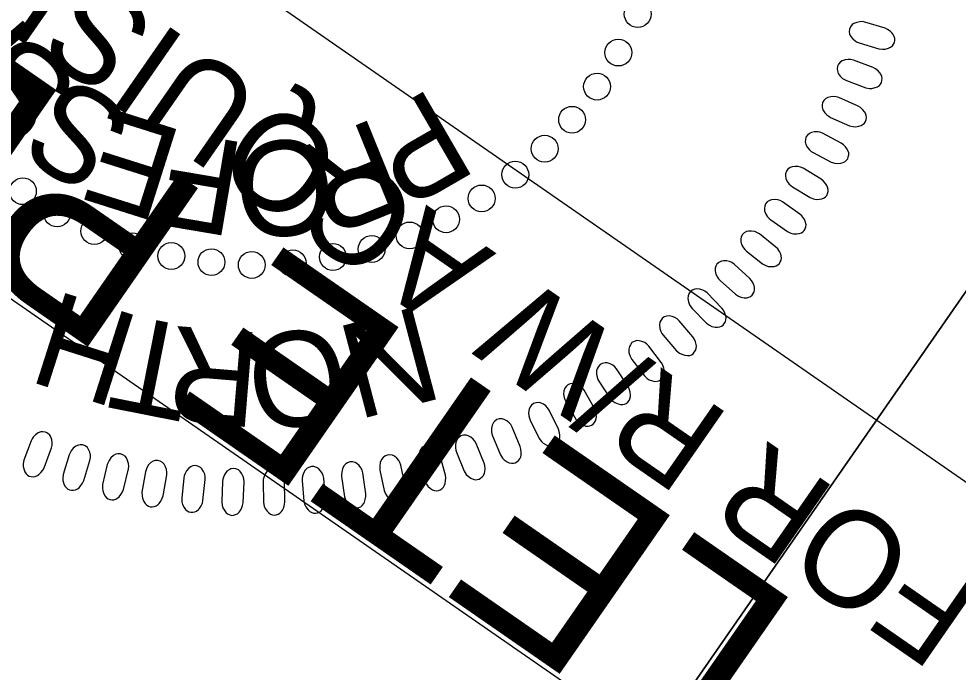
# Model space of a CAD drawing. Extents: x 478372 to 480379, y 492840 to 494699.
# Drawn here: x 478483.3 to 478539.3, y 493813.2 to 493852.2 of the extents above; entities that cross this region are included whole.
import ezdxf

# ---------------------------------------------------------------- set-up
doc = ezdxf.new("R2010")
doc.units = 0
for name, color, linetype in [('Sheet PE Seal Cell', 7, 'Continuous'), ('Sheet Plan CELL', 7, 'Continuous'), ('Sheet Sticker Exception Certification CELL', 7, 'Continuous'), ('Sheet Sticker Incomplete CELL', 7, 'Continuous')]:
    doc.layers.add(name, color=color, linetype=linetype)

msp = doc.modelspace()

# ---------------------------------------------------------------- linework, layer by layer
at = {"layer": 'Sheet PE Seal Cell'}
for points in [[(478533.439, 493850.734), (478534.613, 493850.38), (478534.834, 493850.353), (478534.983, 493850.362), (478535.178, 493850.421), (478535.311, 493850.483), (478535.42, 493850.567), (478535.488, 493850.655), (478535.539, 493850.757), (478535.552, 493850.87), (478535.558, 493850.993), (478535.531, 493851.11), (478535.466, 493851.239), (478535.407, 493851.32), (478535.283, 493851.427), (478535.128, 493851.536), (478534.982, 493851.604), (478533.781, 493851.974), (478533.612, 493852.001), (478533.466, 493851.998), (478533.287, 493851.958), (478533.121, 493851.891), (478533.016, 493851.821), (478532.914, 493851.688), (478532.852, 493851.551), (478532.847, 493851.396), (478532.864, 493851.282), (478532.923, 493851.132), (478533.051, 493850.968), (478533.203, 493850.852), (478533.319, 493850.786)], [(478532.674, 493848.485), (478533.824, 493848.058), (478534.043, 493848.017), (478534.192, 493848.016), (478534.39, 493848.063), (478534.527, 493848.116), (478534.641, 493848.194), (478534.714, 493848.278), (478534.772, 493848.376), (478534.792, 493848.487), (478534.806, 493848.61), (478534.787, 493848.729), (478534.729, 493848.862), (478534.675, 493848.946), (478534.559, 493849.061), (478534.411, 493849.18), (478534.269, 493849.256), (478533.094, 493849.701), (478532.927, 493849.739), (478532.781, 493849.745), (478532.6, 493849.716), (478532.43, 493849.66), (478532.322, 493849.597), (478532.21, 493849.47), (478532.14, 493849.337), (478532.125, 493849.183), (478532.136, 493849.067), (478532.184, 493848.913), (478532.302, 493848.743), (478532.447, 493848.617), (478532.558, 493848.544)], [(478531.734, 493846.288), (478532.855, 493845.79), (478533.071, 493845.735), (478533.219, 493845.725), (478533.42, 493845.759), (478533.56, 493845.803), (478533.678, 493845.874), (478533.757, 493845.953), (478533.821, 493846.047), (478533.848, 493846.158), (478533.869, 493846.279), (478533.857, 493846.399), (478533.808, 493846.535), (478533.76, 493846.622), (478533.651, 493846.745), (478533.511, 493846.872), (478533.374, 493846.958), (478532.229, 493847.475), (478532.065, 493847.523), (478531.919, 493847.539), (478531.737, 493847.522), (478531.564, 493847.476), (478531.451, 493847.42), (478531.333, 493847.301), (478531.254, 493847.172), (478531.23, 493847.019), (478531.233, 493846.903), (478531.272, 493846.747), (478531.379, 493846.569), (478531.516, 493846.434), (478531.622, 493846.355)], [(478530.682, 493844.187), (478531.77, 493843.619), (478531.982, 493843.551), (478532.13, 493843.532), (478532.332, 493843.554), (478532.474, 493843.589), (478532.597, 493843.652), (478532.68, 493843.726), (478532.75, 493843.816), (478532.784, 493843.925), (478532.813, 493844.044), (478532.809, 493844.165), (478532.768, 493844.304), (478532.725, 493844.394), (478532.624, 493844.523), (478532.492, 493844.659), (478532.362, 493844.752), (478531.251, 493845.341), (478531.091, 493845.399), (478530.946, 493845.424), (478530.763, 493845.419), (478530.588, 493845.384), (478530.472, 493845.335), (478530.346, 493845.223), (478530.259, 493845.1), (478530.225, 493844.949), (478530.221, 493844.833), (478530.25, 493844.674), (478530.345, 493844.49), (478530.474, 493844.347), (478530.575, 493844.261)], [(478529.46, 493842.137), (478530.51, 493841.502), (478530.717, 493841.42), (478530.864, 493841.392), (478531.067, 493841.401), (478531.212, 493841.427), (478531.338, 493841.482), (478531.426, 493841.551), (478531.501, 493841.637), (478531.541, 493841.743), (478531.578, 493841.861), (478531.581, 493841.981), (478531.55, 493842.122), (478531.513, 493842.215), (478531.419, 493842.349), (478531.297, 493842.494), (478531.172, 493842.595), (478530.1, 493843.252), (478529.943, 493843.321), (478529.801, 493843.354), (478529.618, 493843.36), (478529.441, 493843.337), (478529.322, 493843.295), (478529.189, 493843.192), (478529.095, 493843.074), (478529.052, 493842.925), (478529.04, 493842.81), (478529.06, 493842.65), (478529.143, 493842.46), (478529.262, 493842.309), (478529.358, 493842.216)], [(478528.16, 493840.17), (478529.168, 493839.47), (478529.369, 493839.376), (478529.514, 493839.339), (478529.717, 493839.335), (478529.863, 493839.352), (478529.992, 493839.399), (478530.084, 493839.462), (478530.165, 493839.543), (478530.212, 493839.646), (478530.256, 493839.761), (478530.267, 493839.881), (478530.244, 493840.024), (478530.213, 493840.119), (478530.128, 493840.26), (478530.015, 493840.411), (478529.897, 493840.52), (478528.868, 493841.243), (478528.717, 493841.321), (478528.576, 493841.364), (478528.394, 493841.381), (478528.215, 493841.369), (478528.094, 493841.335), (478527.956, 493841.24), (478527.854, 493841.128), (478527.802, 493840.982), (478527.783, 493840.868), (478527.792, 493840.707), (478527.863, 493840.512), (478527.973, 493840.354), (478528.062, 493840.256)], [(478526.713, 493838.312), (478527.675, 493837.551), (478527.87, 493837.444), (478528.012, 493837.398), (478528.215, 493837.381), (478528.361, 493837.389), (478528.493, 493837.427), (478528.589, 493837.485), (478528.675, 493837.56), (478528.728, 493837.661), (478528.779, 493837.773), (478528.798, 493837.892), (478528.784, 493838.036), (478528.759, 493838.132), (478528.683, 493838.278), (478528.58, 493838.436), (478528.469, 493838.553), (478527.488, 493839.339), (478527.341, 493839.427), (478527.204, 493839.478), (478527.023, 493839.506), (478526.844, 493839.506), (478526.721, 493839.479), (478526.577, 493839.393), (478526.468, 493839.288), (478526.407, 493839.146), (478526.381, 493839.033), (478526.38, 493838.871), (478526.439, 493838.673), (478526.538, 493838.508), (478526.621, 493838.405)], [(478525.142, 493836.55), (478526.054, 493835.73), (478526.242, 493835.611), (478526.381, 493835.555), (478526.582, 493835.526), (478526.728, 493835.524), (478526.863, 493835.555), (478526.962, 493835.606), (478527.052, 493835.676), (478527.112, 493835.772), (478527.17, 493835.882), (478527.196, 493835.999), (478527.191, 493836.144), (478527.172, 493836.242), (478527.106, 493836.392), (478527.012, 493836.556), (478526.909, 493836.68), (478525.979, 493837.526), (478525.838, 493837.622), (478525.704, 493837.682), (478525.526, 493837.722), (478525.347, 493837.732), (478525.222, 493837.713), (478525.073, 493837.637), (478524.958, 493837.539), (478524.888, 493837.401), (478524.855, 493837.29), (478524.844, 493837.129), (478524.891, 493836.926), (478524.979, 493836.756), (478525.055, 493836.647)], [(478523.477, 493834.888), (478524.336, 493834.012), (478524.516, 493833.881), (478524.651, 493833.817), (478524.851, 493833.775), (478524.996, 493833.765), (478525.133, 493833.787), (478525.235, 493833.831), (478525.329, 493833.895), (478525.395, 493833.988), (478525.459, 493834.093), (478525.492, 493834.209), (478525.497, 493834.354), (478525.484, 493834.453), (478525.428, 493834.607), (478525.344, 493834.777), (478525.249, 493834.906), (478524.374, 493835.81), (478524.239, 493835.914), (478524.109, 493835.982), (478523.934, 493836.034), (478523.756, 493836.055), (478523.631, 493836.044), (478523.477, 493835.977), (478523.356, 493835.886), (478523.277, 493835.753), (478523.238, 493835.644), (478523.217, 493835.484), (478523.25, 493835.279), (478523.328, 493835.104), (478523.397, 493834.99)], [(478521.749, 493833.293), (478522.551, 493832.365), (478522.723, 493832.223), (478522.854, 493832.151), (478523.049, 493832.097), (478523.194, 493832.077), (478523.332, 493832.089), (478523.437, 493832.128), (478523.535, 493832.187), (478523.606, 493832.274), (478523.678, 493832.376), (478523.718, 493832.49), (478523.731, 493832.633), (478523.725, 493832.733), (478523.678, 493832.89), (478523.605, 493833.065), (478523.518, 493833.2), (478522.702, 493834.156), (478522.574, 493834.27), (478522.449, 493834.346), (478522.277, 493834.408), (478522.101, 493834.44), (478521.975, 493834.437), (478521.817, 493834.38), (478521.691, 493834.297), (478521.604, 493834.169), (478521.557, 493834.063), (478521.526, 493833.904), (478521.547, 493833.698), (478521.613, 493833.518), (478521.676, 493833.401)], [(478519.884, 493831.841), (478520.627, 493830.864), (478520.789, 493830.713), (478520.915, 493830.632), (478521.107, 493830.565), (478521.251, 493830.537), (478521.389, 493830.541), (478521.495, 493830.573), (478521.597, 493830.625), (478521.674, 493830.709), (478521.751, 493830.805), (478521.798, 493830.915), (478521.822, 493831.058), (478521.821, 493831.158), (478521.784, 493831.318), (478521.723, 493831.497), (478521.644, 493831.638), (478520.89, 493832.643), (478520.769, 493832.764), (478520.649, 493832.848), (478520.481, 493832.921), (478520.308, 493832.964), (478520.182, 493832.969), (478520.021, 493832.922), (478519.89, 493832.847), (478519.795, 493832.725), (478519.742, 493832.622), (478519.7, 493832.466), (478519.708, 493832.258), (478519.763, 493832.074), (478519.818, 493831.953)], [(478517.917, 493830.541), (478518.596, 493829.52), (478518.749, 493829.358), (478518.87, 493829.27), (478519.057, 493829.191), (478519.199, 493829.154), (478519.336, 493829.15), (478519.446, 493829.175), (478519.55, 493829.22), (478519.632, 493829.299), (478519.715, 493829.39), (478519.769, 493829.497), (478519.801, 493829.638), (478519.807, 493829.738), (478519.78, 493829.9), (478519.73, 493830.083), (478519.661, 493830.228), (478518.971, 493831.278), (478518.858, 493831.407), (478518.743, 493831.498), (478518.581, 493831.582), (478518.41, 493831.636), (478518.285, 493831.648), (478518.12, 493831.612), (478517.986, 493831.545), (478517.883, 493831.429), (478517.824, 493831.329), (478517.773, 493831.176), (478517.767, 493830.969), (478517.811, 493830.782), (478517.858, 493830.657)], [(478515.937, 493829.336), (478516.551, 493828.274), (478516.693, 493828.102), (478516.809, 493828.007), (478516.991, 493827.917), (478517.13, 493827.871), (478517.267, 493827.858), (478517.377, 493827.876), (478517.484, 493827.915), (478517.571, 493827.988), (478517.66, 493828.074), (478517.72, 493828.177), (478517.761, 493828.316), (478517.773, 493828.415), (478517.756, 493828.579), (478517.718, 493828.764), (478517.658, 493828.914), (478517.035, 493830.006), (478516.931, 493830.141), (478516.822, 493830.239), (478516.665, 493830.332), (478516.498, 493830.397), (478516.374, 493830.417), (478516.208, 493830.391), (478516.068, 493830.333), (478515.96, 493830.224), (478515.893, 493830.128), (478515.833, 493829.978), (478515.814, 493829.772), (478515.846, 493829.583), (478515.886, 493829.455)], [(478513.816, 493828.223), (478514.362, 493827.124), (478514.493, 493826.944), (478514.602, 493826.842), (478514.778, 493826.741), (478514.914, 493826.686), (478515.05, 493826.664), (478515.161, 493826.675), (478515.27, 493826.707), (478515.362, 493826.775), (478515.456, 493826.855), (478515.523, 493826.955), (478515.572, 493827.091), (478515.59, 493827.189), (478515.584, 493827.353), (478515.557, 493827.54), (478515.506, 493827.693), (478514.954, 493828.821), (478514.858, 493828.963), (478514.756, 493829.068), (478514.605, 493829.171), (478514.442, 493829.247), (478514.319, 493829.275), (478514.152, 493829.259), (478514.009, 493829.209), (478513.894, 493829.107), (478513.822, 493829.017), (478513.752, 493828.87), (478513.721, 493828.666), (478513.741, 493828.475), (478513.771, 493828.345)], [(478511.577, 493827.282), (478512.053, 493826.152), (478512.172, 493825.964), (478512.274, 493825.855), (478512.444, 493825.742), (478512.576, 493825.679), (478512.71, 493825.649), (478512.822, 493825.653), (478512.934, 493825.678), (478513.029, 493825.74), (478513.127, 493825.814), (478513.201, 493825.91), (478513.258, 493826.042), (478513.283, 493826.139), (478513.287, 493826.303), (478513.272, 493826.492), (478513.231, 493826.647), (478512.75, 493827.808), (478512.663, 493827.956), (478512.568, 493828.067), (478512.424, 493828.179), (478512.266, 493828.265), (478512.146, 493828.301), (478511.977, 493828.294), (478511.832, 493828.255), (478511.71, 493828.16), (478511.633, 493828.074), (478511.554, 493827.932), (478511.51, 493827.73), (478511.517, 493827.538), (478511.54, 493827.407)], [(478484.063, 493826.981), (478483.636, 493825.831), (478483.595, 493825.612), (478483.595, 493825.463), (478483.641, 493825.265), (478483.694, 493825.129), (478483.771, 493825.015), (478483.856, 493824.94), (478483.954, 493824.883), (478484.066, 493824.862), (478484.188, 493824.849), (478484.307, 493824.869), (478484.44, 493824.926), (478484.524, 493824.98), (478484.639, 493825.097), (478484.757, 493825.244), (478484.834, 493825.386), (478485.278, 493826.561), (478485.317, 493826.728), (478485.323, 493826.875), (478485.294, 493827.055), (478485.238, 493827.225), (478485.174, 493827.334), (478485.048, 493827.445), (478484.915, 493827.515), (478484.761, 493827.53), (478484.646, 493827.52), (478484.492, 493827.47), (478484.321, 493827.353), (478484.195, 493827.208), (478484.122, 493827.098)], [(478509.426, 493826.312), (478509.893, 493825.178), (478510.011, 493824.989), (478510.113, 493824.88), (478510.281, 493824.766), (478510.413, 493824.701), (478510.546, 493824.671), (478510.658, 493824.673), (478510.77, 493824.698), (478510.866, 493824.759), (478510.965, 493824.832), (478511.039, 493824.927), (478511.098, 493825.059), (478511.123, 493825.156), (478511.128, 493825.32), (478511.115, 493825.509), (478511.075, 493825.664), (478510.604, 493826.829), (478510.518, 493826.978), (478510.424, 493827.089), (478510.28, 493827.203), (478510.123, 493827.289), (478510.002, 493827.326), (478509.835, 493827.321), (478509.689, 493827.283), (478509.566, 493827.189), (478509.488, 493827.103), (478509.408, 493826.963), (478509.363, 493826.761), (478509.369, 493826.569), (478509.391, 493826.438)], [(478486.334, 493826.161), (478485.98, 493824.986), (478485.952, 493824.766), (478485.962, 493824.617), (478486.02, 493824.422), (478486.082, 493824.289), (478486.166, 493824.18), (478486.255, 493824.111), (478486.357, 493824.06), (478486.47, 493824.046), (478486.593, 493824.041), (478486.71, 493824.068), (478486.839, 493824.133), (478486.92, 493824.193), (478487.027, 493824.316), (478487.136, 493824.471), (478487.204, 493824.618), (478487.574, 493825.818), (478487.601, 493825.987), (478487.598, 493826.134), (478487.559, 493826.312), (478487.491, 493826.478), (478487.421, 493826.583), (478487.288, 493826.686), (478487.151, 493826.748), (478486.996, 493826.753), (478486.881, 493826.735), (478486.731, 493826.676), (478486.568, 493826.548), (478486.452, 493826.396), (478486.385, 493826.28)], [(478507.203, 493825.782), (478507.533, 493824.601), (478507.629, 493824.4), (478507.717, 493824.279), (478507.87, 493824.146), (478507.993, 493824.067), (478508.123, 493824.021), (478508.234, 493824.01), (478508.348, 493824.021), (478508.451, 493824.07), (478508.557, 493824.132), (478508.643, 493824.217), (478508.716, 493824.342), (478508.752, 493824.435), (478508.777, 493824.597), (478508.786, 493824.786), (478508.765, 493824.945), (478508.433, 493826.158), (478508.366, 493826.315), (478508.285, 493826.437), (478508.156, 493826.567), (478508.01, 493826.671), (478507.895, 493826.721), (478507.728, 493826.737), (478507.579, 493826.716), (478507.445, 493826.637), (478507.358, 493826.561), (478507.262, 493826.431), (478507.193, 493826.235), (478507.176, 493826.044), (478507.183, 493825.911)], [(478488.608, 493825.577), (478488.328, 493824.383), (478488.315, 493824.16), (478488.333, 493824.013), (478488.404, 493823.822), (478488.474, 493823.693), (478488.565, 493823.59), (478488.658, 493823.527), (478488.762, 493823.483), (478488.876, 493823.476), (478488.999, 493823.478), (478489.115, 493823.512), (478489.24, 493823.586), (478489.316, 493823.65), (478489.416, 493823.78), (478489.514, 493823.941), (478489.573, 493824.091), (478489.866, 493825.313), (478489.883, 493825.483), (478489.871, 493825.63), (478489.82, 493825.806), (478489.743, 493825.967), (478489.667, 493826.067), (478489.527, 493826.161), (478489.386, 493826.214), (478489.231, 493826.209), (478489.118, 493826.185), (478488.972, 493826.117), (478488.816, 493825.979), (478488.71, 493825.819), (478488.652, 493825.7)], [(478490.879, 493825.137), (478490.675, 493823.927), (478490.676, 493823.705), (478490.704, 493823.558), (478490.786, 493823.372), (478490.864, 493823.248), (478490.961, 493823.151), (478491.058, 493823.094), (478491.165, 493823.056), (478491.279, 493823.057), (478491.402, 493823.066), (478491.515, 493823.108), (478491.635, 493823.189), (478491.707, 493823.258), (478491.798, 493823.394), (478491.887, 493823.561), (478491.936, 493823.715), (478492.151, 493824.952), (478492.158, 493825.124), (478492.137, 493825.269), (478492.075, 493825.441), (478491.987, 493825.597), (478491.905, 493825.692), (478491.76, 493825.777), (478491.616, 493825.822), (478491.462, 493825.807), (478491.35, 493825.775), (478491.209, 493825.698), (478491.062, 493825.551), (478490.966, 493825.385), (478490.915, 493825.262)], [(478502.576, 493824.859), (478502.756, 493823.645), (478502.825, 493823.434), (478502.897, 493823.303), (478503.033, 493823.152), (478503.145, 493823.058), (478503.267, 493822.995), (478503.377, 493822.971), (478503.491, 493822.968), (478503.599, 493823.004), (478503.713, 493823.051), (478503.808, 493823.126), (478503.897, 493823.24), (478503.944, 493823.327), (478503.989, 493823.485), (478504.021, 493823.671), (478504.02, 493823.832), (478503.843, 493825.077), (478503.797, 493825.241), (478503.731, 493825.372), (478503.619, 493825.517), (478503.488, 493825.64), (478503.38, 493825.704), (478503.216, 493825.74), (478503.065, 493825.738), (478502.923, 493825.676), (478502.827, 493825.612), (478502.716, 493825.495), (478502.622, 493825.31), (478502.582, 493825.122), (478502.572, 493824.989)], [(478504.859, 493825.234), (478505.115, 493824.034), (478505.197, 493823.827), (478505.277, 493823.702), (478505.423, 493823.559), (478505.54, 493823.472), (478505.667, 493823.417), (478505.777, 493823.4), (478505.891, 493823.404), (478505.996, 493823.447), (478506.107, 493823.501), (478506.197, 493823.581), (478506.279, 493823.7), (478506.321, 493823.791), (478506.356, 493823.952), (478506.376, 493824.14), (478506.366, 493824.3), (478506.111, 493825.531), (478506.053, 493825.692), (478505.98, 493825.819), (478505.859, 493825.957), (478505.72, 493826.069), (478505.609, 493826.128), (478505.443, 493826.154), (478505.292, 493826.142), (478505.155, 493826.071), (478505.063, 493826.001), (478504.959, 493825.877), (478504.877, 493825.686), (478504.849, 493825.496), (478504.847, 493825.364)], [(478493.169, 493824.783), (478493.041, 493823.562), (478493.055, 493823.34), (478493.093, 493823.196), (478493.186, 493823.016), (478493.272, 493822.896), (478493.375, 493822.805), (478493.475, 493822.755), (478493.585, 493822.723), (478493.698, 493822.731), (478493.82, 493822.749), (478493.93, 493822.797), (478494.045, 493822.886), (478494.113, 493822.959), (478494.195, 493823.101), (478494.274, 493823.273), (478494.312, 493823.43), (478494.45, 493824.679), (478494.446, 493824.849), (478494.415, 493824.993), (478494.343, 493825.16), (478494.246, 493825.312), (478494.158, 493825.401), (478494.008, 493825.477), (478493.861, 493825.512), (478493.708, 493825.488), (478493.599, 493825.45), (478493.462, 493825.363), (478493.326, 493825.207), (478493.24, 493825.036), (478493.197, 493824.91)], [(478495.477, 493824.571), (478495.427, 493823.345), (478495.455, 493823.124), (478495.501, 493822.983), (478495.606, 493822.809), (478495.699, 493822.695), (478495.807, 493822.611), (478495.91, 493822.567), (478496.022, 493822.542), (478496.135, 493822.557), (478496.255, 493822.583), (478496.362, 493822.638), (478496.471, 493822.733), (478496.534, 493822.81), (478496.608, 493822.957), (478496.674, 493823.134), (478496.704, 493823.293), (478496.763, 493824.548), (478496.748, 493824.718), (478496.708, 493824.86), (478496.625, 493825.023), (478496.519, 493825.167), (478496.426, 493825.251), (478496.271, 493825.317), (478496.122, 493825.343), (478495.971, 493825.309), (478495.865, 493825.264), (478495.733, 493825.17), (478495.607, 493825.005), (478495.533, 493824.828), (478495.497, 493824.7)], [(478497.893, 493824.544), (478497.92, 493823.317), (478497.962, 493823.099), (478498.016, 493822.96), (478498.133, 493822.793), (478498.232, 493822.686), (478498.346, 493822.608), (478498.452, 493822.57), (478498.564, 493822.553), (478498.676, 493822.575), (478498.794, 493822.608), (478498.898, 493822.67), (478499, 493822.772), (478499.058, 493822.853), (478499.123, 493823.004), (478499.179, 493823.185), (478499.197, 493823.345), (478499.178, 493824.601), (478499.152, 493824.77), (478499.104, 493824.909), (478499.011, 493825.067), (478498.896, 493825.204), (478498.797, 493825.282), (478498.639, 493825.338), (478498.489, 493825.354), (478498.34, 493825.311), (478498.237, 493825.259), (478498.112, 493825.157), (478497.996, 493824.985), (478497.932, 493824.804), (478497.905, 493824.673)], [(478500.23, 493824.613), (478500.333, 493823.391), (478500.389, 493823.176), (478500.453, 493823.041), (478500.579, 493822.881), (478500.684, 493822.78), (478500.803, 493822.71), (478500.911, 493822.68), (478501.025, 493822.669), (478501.135, 493822.698), (478501.251, 493822.738), (478501.351, 493822.806), (478501.446, 493822.915), (478501.499, 493822.999), (478501.554, 493823.154), (478501.599, 493823.338), (478501.607, 493823.499), (478501.509, 493824.751), (478501.472, 493824.919), (478501.415, 493825.054), (478501.313, 493825.205), (478501.189, 493825.335), (478501.086, 493825.406), (478500.924, 493825.453), (478500.773, 493825.46), (478500.628, 493825.407), (478500.528, 493825.349), (478500.41, 493825.239), (478500.305, 493825.06), (478500.253, 493824.876), (478500.234, 493824.744)]]:
    msp.add_lwpolyline(points, close=True, dxfattribs=at)
for centre in [(478520.233, 493852.454), (478519.073, 493850.156), (478517.808, 493848.124), (478516.319, 493846.146), (478514.684, 493844.419), (478512.931, 493842.872), (478483.572, 493841.883), (478510.927, 493841.451), (478485.613, 493840.564), (478508.804, 493840.208), (478487.835, 493839.506), (478506.632, 493839.243), (478490.115, 493838.602), (478504.374, 493838.434), (478492.424, 493838.018), (478502.056, 493837.958), (478494.815, 493837.65), (478497.22, 493837.484), (478499.663, 493837.582)]:
    msp.add_circle(centre, 0.801, dxfattribs=at)
at = {"layer": 'Sheet Plan CELL'}
msp.add_line((478502.42, 493782.012), (478566.511, 493874.425), dxfattribs=at)
for points in [[(478502.42, 493782.012), (478420.257, 493838.992), (478484.376, 493931.446), (478566.55, 493874.459)], [(478584.628, 493724.986), (478502.42, 493782.012), (478566.55, 493874.459), (478648.732, 493817.42)]]:
    msp.add_lwpolyline(points, close=True, dxfattribs=at)
at = {"layer": 'Sheet Sticker Incomplete CELL'}
msp.add_lwpolyline([(478594.874, 493786.337), (478581.479, 493767.028), (478460.695, 493850.814), (478474.089, 493870.123)], close=True, dxfattribs=at)

# ---------------------------------------------------------------- texts
at = {"layer": 'Sheet PE Seal Cell'}
for s, rotation, p in [('I', 130.661, (478484.492, 493850.996)), ('S', 138.6008, (478487.255, 493848.31)), ('S', 146.5406, (478490.485, 493846.193)), ('P', 210.059, (478507.957, 493848.124)), ('E', 162.4202, (478493.306, 493845.404)), ('R', 202.1192, (478504.655, 493846.323)), ('F', 170.36, (478496.968, 493844.736)), ('O', 186.2396, (478501.795, 493845.208)), ('H', 162.3074, (478490.73, 493834.328)), ('N', 194.7541, (478507.357, 493835.101)), ('T', 168.7967, (478494.145, 493833.675)), ('R', 175.2861, (478497.886, 493833.415)), ('O', 188.2648, (478502.467, 493833.923))]:
    msp.add_text(s, height=5.669, rotation=rotation, dxfattribs=at).set_placement(p)
at = {"layer": 'Sheet Sticker Exception Certification CELL'}
for s, p in [('UNLESS ALL SIGNATURES COMPLETED', (478646.498, 493842.27)), ('UNLESS ALL SIGNATURES COMPLETED', (478646.498, 493842.27)), ('DOCUMENT NOT CONSIDERED FINAL', (478637.316, 493837.93)), ('DOCUMENT NOT CONSIDERED FINAL', (478637.316, 493837.93))]:
    msp.add_text(s, height=5.5, rotation=145.2516, dxfattribs=at).set_placement(p)
at = {"layer": 'Sheet Sticker Incomplete CELL'}
for s, height, p in [('INCOMPLETE PLANS', 11.52, (478580.851, 493781.825)), ('DO NOT USE FOR R/W ACQUISITION', 5.76, (478582.142, 493789.388))]:
    msp.add_text(s, height=height, rotation=145.2516, dxfattribs=at).set_placement(p)

doc.saveas('drawing.dxf')
